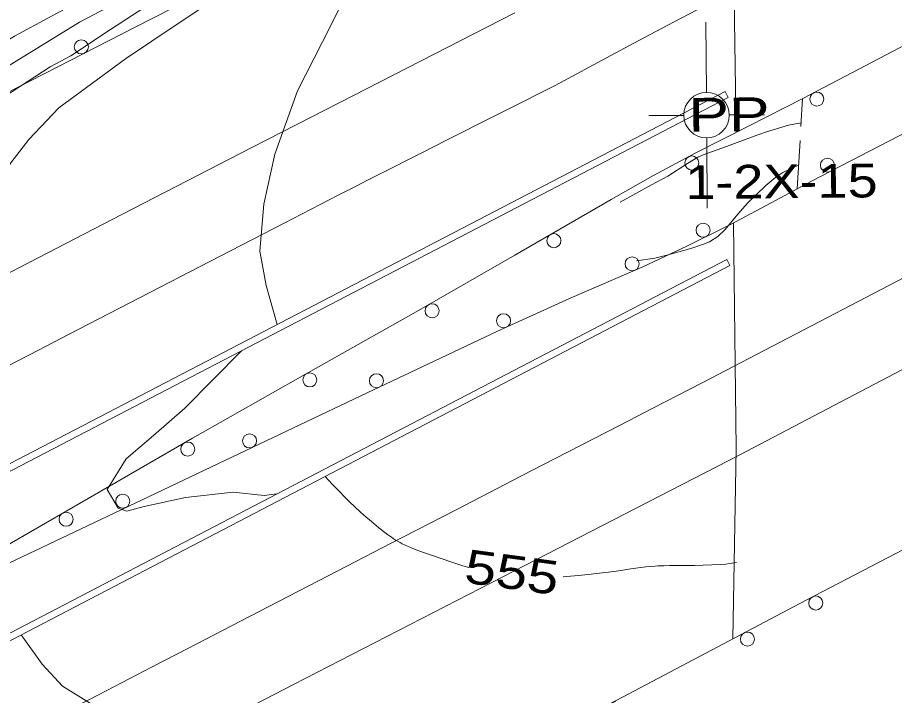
# Model space of a CAD drawing. Extents: x 2361284 to 2366480, y 6976556 to 6985346.
# Drawn here: x 2361505.4 to 2361630.3, y 6977542.1 to 6977638.7 of the extents above; entities that cross this region are included whole.
import ezdxf
from ezdxf.enums import TextEntityAlignment as Align

# ---------------------------------------------------------------- set-up
doc = ezdxf.new("R2010")
doc.units = 0
doc.header["$LTSCALE"] = 1.9
for name, color, linetype, lineweight in [('12', 7, 'Continuous', 13), ('13', 7, 'Continuous', 13), ('14', 7, 'Continuous', 13), ('17', 7, 'Continuous', 13), ('2', 7, 'Continuous', 13), ('24', 7, 'Continuous', 13), ('3', 7, 'Continuous', 13), ('8', 7, 'Continuous', 13)]:
    doc.layers.add(name, color=color, linetype=linetype, lineweight=lineweight)

msp = doc.modelspace()

# ---------------------------------------------------------------- linework, layer by layer
at = {"layer": '12'}
for points in [[(2361566.852, 6977658.025), (2361564.089, 6977656.38), (2361562.211, 6977655.042), (2361560.039, 6977653.14), (2361559.122, 6977651.842), (2361555.516, 6977647.187), (2361553.059, 6977643.544), (2361548.878, 6977635.233), (2361545.314, 6977628.259), (2361542.08, 6977619.208), (2361540.528, 6977612.103), (2361539.931, 6977605.426), (2361540.838, 6977600.495), (2361542.431, 6977594.95)], [(2361542.39, 6977570.849), (2361540.582, 6977570.592), (2361536.148, 6977571.1), (2361529.384, 6977570.345), (2361523.486, 6977569.029), (2361521.021, 6977568.388), (2361519.788, 6977568.834), (2361518.183, 6977571.489), (2361520.922, 6977575.834), (2361524.82, 6977579.151), (2361529.273, 6977583.044), (2361537.316, 6977591.202)], [(2361569.701, 6977560.347), (2361568.843, 6977560.619), (2361567.153, 6977561.183), (2361564.552, 6977562.063), (2361563.257, 6977562.517), (2361561.967, 6977562.991), (2361561.324, 6977563.238), (2361561.097, 6977563.33), (2361560.65, 6977563.528), (2361560.212, 6977563.745), (2361559.925, 6977563.899), (2361559.362, 6977564.228), (2361558.949, 6977564.49), (2361558.677, 6977564.672), (2361558.143, 6977565.051), (2361557.359, 6977565.648), (2361556.846, 6977566.061), (2361555.839, 6977566.907), (2361554.779, 6977567.823), (2361554.258, 6977568.287), (2361553.486, 6977568.992), (2361552.73, 6977569.715), (2361552.358, 6977570.084), (2361550.955, 6977571.51), (2361550.264, 6977572.231), (2361549.247, 6977573.334)], [(2361607.817, 6977561.059), (2361606.825, 6977560.91), (2361606.328, 6977560.849), (2361605.579, 6977560.788), (2361604.337, 6977560.732), (2361601.851, 6977560.653), (2361601.227, 6977560.64), (2361599.977, 6977560.632), (2361598.311, 6977560.626), (2361597.478, 6977560.612), (2361596.646, 6977560.582), (2361596.23, 6977560.559), (2361595.432, 6977560.497), (2361594.902, 6977560.444), (2361593.844, 6977560.316), (2361592.788, 6977560.167), (2361591.381, 6977559.956), (2361590.677, 6977559.851), (2361589.62, 6977559.706), (2361589.09, 6977559.641), (2361587.113, 6977559.423), (2361585.794, 6977559.289), (2361583.155, 6977559.045)]]:
    msp.add_lwpolyline(points, dxfattribs=at)
at = {"layer": '13'}
for points in [[(2361374.278, 6977534.278), (2361374.277, 6977534.358), (2361374.927, 6977538.594), (2361376.894, 6977546.253), (2361379.575, 6977551.519), (2361384.549, 6977557.517), (2361389.33, 6977562.622), (2361395.696, 6977568.314), (2361407.053, 6977576.051), (2361419.518, 6977584.01), (2361434.624, 6977592.925), (2361454.091, 6977603.9), (2361472.258, 6977615.944), (2361482.609, 6977622.103), (2361490.422, 6977627.187), (2361505.009, 6977636.036), (2361525.345, 6977647.02), (2361533.907, 6977652.212), (2361547.702, 6977660.043), (2361554.261, 6977663.506), (2361560.005, 6977666.201), (2361561.726, 6977667.227)], [(2361408.786, 6977538.956), (2361407.924, 6977543.439), (2361407.448, 6977547.144), (2361407.123, 6977551.881), (2361407.629, 6977555.446), (2361409.683, 6977560.336), (2361415.194, 6977567.659), (2361421.913, 6977574.173), (2361427.945, 6977579.09), (2361436.505, 6977586.572), (2361443.195, 6977591.817), (2361449.5, 6977597.707), (2361457.518, 6977603.192), (2361469.589, 6977610.568), (2361485.682, 6977619.712), (2361500.867, 6977629.816), (2361514.26, 6977638.034), (2361522.051, 6977642.129), (2361536.104, 6977650.433), (2361550.883, 6977658.904), (2361557.304, 6977662.145), (2361560.675, 6977664.107), (2361562.954, 6977665.289)], [(2361497.875, 6977623.748), (2361510.08, 6977631.663), (2361513.025, 6977633.242), (2361518.67, 6977636.986), (2361529.573, 6977644.09), (2361539.627, 6977650.006), (2361544.025, 6977652.328), (2361555.912, 6977659.171), (2361559.224, 6977661.013), (2361561.165, 6977662.031), (2361562.248, 6977662.742), (2361563.843, 6977663.317)], [(2361498.188, 6977571.919), (2361497.192, 6977573.548), (2361496.122, 6977575.658), (2361494.725, 6977578.505), (2361493.653, 6977580.855), (2361493.044, 6977583.849), (2361493.018, 6977586.649), (2361493.17, 6977591.692), (2361494.364, 6977597.493), (2361495.675, 6977601.695), (2361498.586, 6977607.843), (2361501.458, 6977612.892), (2361504.5, 6977618.001), (2361507.029, 6977621.285), (2361511.326, 6977625.816), (2361520.8, 6977632.796), (2361528.323, 6977637.818), (2361534.117, 6977641.733), (2361538.632, 6977645.306), (2361547.085, 6977651.307), (2361555.326, 6977655.597), (2361560.625, 6977658.896), (2361563.638, 6977660.695), (2361564.928, 6977661.567)], [(2361617.042, 6977623.681), (2361615.225, 6977623.334), (2361611.944, 6977622.359), (2361610.33, 6977621.797), (2361606.424, 6977620.31), (2361603.105, 6977619.138), (2361602.33, 6977618.773), (2361600.856, 6977617.897), (2361598.062, 6977616.1), (2361595.744, 6977614.828), (2361591.268, 6977612.365)], [(2361616.689, 6977617.697), (2361614.456, 6977616.627), (2361613.446, 6977615.926), (2361612.033, 6977614.74), (2361609.381, 6977612.238), (2361608.004, 6977610.664), (2361606.23, 6977608.494), (2361605.195, 6977607.517), (2361603.998, 6977606.755), (2361603.138, 6977606.38), (2361601.341, 6977605.79), (2361597.916, 6977604.818), (2361596.194, 6977604.423), (2361593.577, 6977604.016)], [(2361590.664, 6977541.315), (2361588.534, 6977540.235), (2361584.915, 6977539.091), (2361580.887, 6977537.842), (2361576.995, 6977536.905), (2361571.938, 6977536.447), (2361566.386, 6977535.644), (2361561.404, 6977534.907), (2361556.137, 6977534.527), (2361552.435, 6977534.562), (2361547.559, 6977534.205), (2361542.013, 6977533.753), (2361537.156, 6977534.516), (2361532.461, 6977536.082), (2361527.718, 6977537.297), (2361520.188, 6977539.405), (2361516.054, 6977540.876), (2361511.869, 6977543.467), (2361508.939, 6977546.589), (2361505.939, 6977550.77)]]:
    msp.add_lwpolyline(points, dxfattribs=at)
at = {"layer": '14'}
for points in [[(2362336.196, 6978020.751), (2362289.743, 6977996.598), (2362266.509, 6977984.536), (2362231.647, 6977966.464), (2362216.707, 6977958.733), (2362186.815, 6977943.294), (2362146.952, 6977922.724), (2362127.025, 6977912.43), (2362107.105, 6977902.122), (2362097.149, 6977896.96), (2361950.117, 6977820.669), (2361779.062, 6977731.907), (2361759.144, 6977721.566), (2361719.322, 6977700.861), (2361679.514, 6977680.127), (2361652.984, 6977666.288), (2361635.3, 6977657.057), (2361599.94, 6977638.579), (2361597.938, 6977637.528), (2361593.941, 6977635.411), (2361589.954, 6977633.278), (2361581.99, 6977628.988)], [(2362357.13, 6977978.417), (2362333.051, 6977965.885), (2362284.884, 6977940.838), (2362239.217, 6977917.125), (2362178.318, 6977885.528), (2362147.872, 6977869.721), (2362131.634, 6977861.279), (2362099.169, 6977844.373), (2362034.251, 6977810.537), (2362001.777, 6977793.649), (2361985.52, 6977785.217), (2361952.988, 6977768.387), (2361887.903, 6977734.767), (2361866.217, 6977723.542), (2361855.379, 6977717.921), (2361792.128, 6977685.082), (2361760.507, 6977668.653), (2361713.084, 6977643.995), (2361639.646, 6977605.776), (2361602.933, 6977586.654)], [(2361608.311, 6977576.395), (2361637.079, 6977591.488), (2361651.468, 6977599.026), (2361673.059, 6977610.318), (2361694.658, 6977621.594), (2361705.461, 6977627.225), (2361727.074, 6977638.473), (2361737.885, 6977644.09), (2361754.106, 6977652.505), (2361766.325, 6977658.829), (2361790.781, 6977671.445), (2361823.4, 6977688.244), (2361839.705, 6977696.653), (2361856, 6977705.081), (2361864.142, 6977709.305), (2362043.714, 6977802.597), (2362187.213, 6977877.097), (2362199.118, 6977883.286), (2362222.92, 6977895.681), (2362246.712, 6977908.095), (2362294.278, 6977932.957)], [(2361576.251, 6977639.334), (2361551.364, 6977626.597), (2361538.928, 6977620.215), (2361520.283, 6977610.624), (2361501.649, 6977601.01), (2361492.337, 6977596.194), (2361468.981, 6977584.091), (2361457.307, 6977578.03), (2361439.803, 6977568.927), (2361413.562, 6977555.246), (2361387.339, 6977541.529), (2361374.234, 6977534.657)], [(2361504.089, 6977589.064), (2361508.406, 6977591.297), (2361512.723, 6977593.53), (2361518.479, 6977596.507), (2361521.357, 6977597.995), (2361529.992, 6977602.457), (2361535.749, 6977605.431), (2361543.426, 6977609.395), (2361547.265, 6977611.377), (2361548.547, 6977612.038), (2361551.112, 6977613.357), (2361553.678, 6977614.672), (2361555.391, 6977615.547), (2361556.532, 6977616.129), (2361558.817, 6977617.292), (2361561.388, 6977618.599), (2361563.103, 6977619.468), (2361566.535, 6977621.204), (2361568.251, 6977622.071), (2361571.685, 6977623.802), (2361575.119, 6977625.532), (2361581.99, 6977628.988)], [(2361602.933, 6977586.654), (2361595.923, 6977583.042), (2361591.251, 6977580.633), (2361581.906, 6977575.814), (2361577.235, 6977573.404), (2361567.892, 6977568.581), (2361558.55, 6977563.757), (2361552.323, 6977560.54), (2361539.869, 6977554.103), (2361529.688, 6977548.838), (2361524.599, 6977546.205), (2361516.965, 6977542.253), (2361505.515, 6977536.324)], [(2361405.339, 6977471.359), (2361429.422, 6977483.918), (2361441.467, 6977490.19), (2361459.539, 6977499.589), (2361486.66, 6977513.665), (2361512.46, 6977527.021), (2361525.364, 6977533.69), (2361544.728, 6977543.68), (2361572.981, 6977558.232), (2361587.111, 6977565.502), (2361608.311, 6977576.395)]]:
    msp.add_lwpolyline(points, dxfattribs=at)
at = {"layer": '17'}
for points in [[(2362373.397, 6977947.2), (2362350.564, 6977935.712), (2362327.814, 6977924.075), (2362278.276, 6977898.373), (2362228.759, 6977872.63), (2362177.351, 6977845.89), (2362125.941, 6977819.15), (2362071.229, 6977790.689), (2362016.516, 6977762.236), (2361978.283, 6977742.433), (2361940.018, 6977722.687), (2361909.694, 6977707.168), (2361879.38, 6977691.638), (2361844.272, 6977673.324), (2361809.175, 6977655), (2361790.913, 6977645.585), (2361772.651, 6977636.161), (2361695.18, 6977595.993), (2361617.768, 6977555.724)], [(2361914.109, 6977775.103), (2361909.826, 6977773.222), (2361905.564, 6977771.303), (2361891.944, 6977764.983), (2361878.322, 6977758.662), (2361861.864, 6977751.035), (2361845.426, 6977743.37), (2361828.273, 6977735.185), (2361811.151, 6977726.912), (2361800.938, 6977721.995), (2361790.733, 6977717.067), (2361781.377, 6977712.518), (2361772.05, 6977707.88), (2361694.578, 6977667.69), (2361617.289, 6977627.154), (2361609.626, 6977623.26), (2361601.962, 6977619.357), (2361595.942, 6977616.13), (2361589.974, 6977612.783)], [(2361594.505, 6977603.175), (2361600.778, 6977606.115), (2361606.969, 6977609.214), (2361612.75, 6977612.28), (2361618.521, 6977615.355), (2361695.785, 6977655.382), (2361772.977, 6977695.557), (2361792.478, 6977706.024), (2361811.828, 6977716.747), (2361835.72, 6977730.296), (2361859.562, 6977743.914), (2361881.423, 6977756.522), (2361903.294, 6977769.121), (2361908.687, 6977772.143), (2361914.109, 6977775.103)], [(2361363.987, 6977555.491), (2361404.158, 6977576.644), (2361444.472, 6977597.539), (2361483.284, 6977617.389), (2361522.098, 6977637.239), (2361544.012, 6977648.438), (2361565.917, 6977659.647)], [(2361589.974, 6977612.783), (2361576.279, 6977604.842), (2361562.544, 6977596.962), (2361546.458, 6977587.868), (2361530.374, 6977578.774), (2361516.39, 6977570.712), (2361502.396, 6977562.637), (2361489.048, 6977555.03), (2361475.679, 6977547.463)], [(2361475.679, 6977547.463), (2361487.626, 6977553.126), (2361499.573, 6977558.8), (2361517.283, 6977567.21), (2361534.985, 6977575.618), (2361554.339, 6977584.802), (2361573.692, 6977593.968), (2361584.058, 6977598.666), (2361594.505, 6977603.175)], [(2361617.768, 6977555.724), (2361591.589, 6977541.884), (2361565.348, 6977528.174), (2361526.844, 6977508.337), (2361488.34, 6977488.51), (2361451.421, 6977469.387), (2361414.51, 6977450.236)]]:
    msp.add_lwpolyline(points, dxfattribs=at)
for centre in [(2361514.525, 6977634.489), (2361619.274, 6977627.065), (2361601.476, 6977617.962), (2361620.785, 6977617.653), (2361603.078, 6977608.387), (2361581.824, 6977606.903), (2361592.966, 6977603.6), (2361564.486, 6977596.923), (2361574.659, 6977595.503), (2361547.074, 6977587.07), (2361556.558, 6977586.958), (2361529.679, 6977577.219), (2361538.487, 6977578.387), (2361520.42, 6977569.807), (2361512.354, 6977567.226), (2361619.128, 6977555.304), (2361609.395, 6977550.166)]:
    msp.add_circle(centre, 1, dxfattribs=at)
at = {"layer": '2'}
for p, q in [((2361603.541, 6977628.01), (2361603.466, 6977638.01)), ((2361600.332, 6977624.739), (2361595.332, 6977624.702)), ((2361603.572, 6977624.77), (2361603.571, 6977624.81)), ((2361606.812, 6977624.801), (2361611.812, 6977624.838)), ((2361603.603, 6977621.53), (2361603.678, 6977611.53))]:
    msp.add_line(p, q, dxfattribs=at)
msp.add_circle((2361603.572, 6977624.77), 3.24, dxfattribs=at)
at = {"layer": '24'}
for p, q in [((2361617.249, 6977627.133), (2361617.017, 6977623.141)), ((2361616.896, 6977621.14), (2361616.491, 6977614.275))]:
    msp.add_line(p, q, dxfattribs=at)
at = {"layer": '3'}
for p, q in [((2361606.209, 6977628.148), (2361606.657, 6977627.292)), ((2361606.447, 6977604.208), (2361606.895, 6977603.353))]:
    msp.add_line(p, q, dxfattribs=at)
for points in [[(2361606.209, 6977628.148), (2361506.597, 6977576.298), (2361384.902, 6977512.948)], [(2361606.657, 6977627.292), (2361507.045, 6977575.442), (2361385.351, 6977512.092)], [(2361394.326, 6977493.716), (2361494.196, 6977545.748), (2361606.447, 6977604.208)], [(2361394.774, 6977492.86), (2361494.645, 6977544.894), (2361606.895, 6977603.353)]]:
    msp.add_lwpolyline(points, dxfattribs=at)
at = {"layer": '8'}
for p, q in [((2361607.795, 6977622.323), (2361606.954, 6977681.319)), ((2361607.783, 6977577.25), (2361607.397, 6977609.438)), ((2361607.783, 6977577.25), (2361607.3, 6977550.224))]:
    msp.add_line(p, q, dxfattribs=at)

# ---------------------------------------------------------------- texts
at = {"layer": '12', "width": 1.25}
msp.add_text(' 555 ', height=4.799, rotation=352.231, dxfattribs=at).set_placement((2361575.542, 6977557.326), align=Align.CENTER)
at = {"layer": '2'}
for s, width, p in [('  PP', 1.35, (2361596.193, 6977622.373)), ('  1-2X-15', 1.2, (2361596.284, 6977612.773))]:
    msp.add_text(s, height=4.799, rotation=0.545, dxfattribs=dict(at, width=width)).set_placement(p)

doc.saveas('drawing.dxf')
